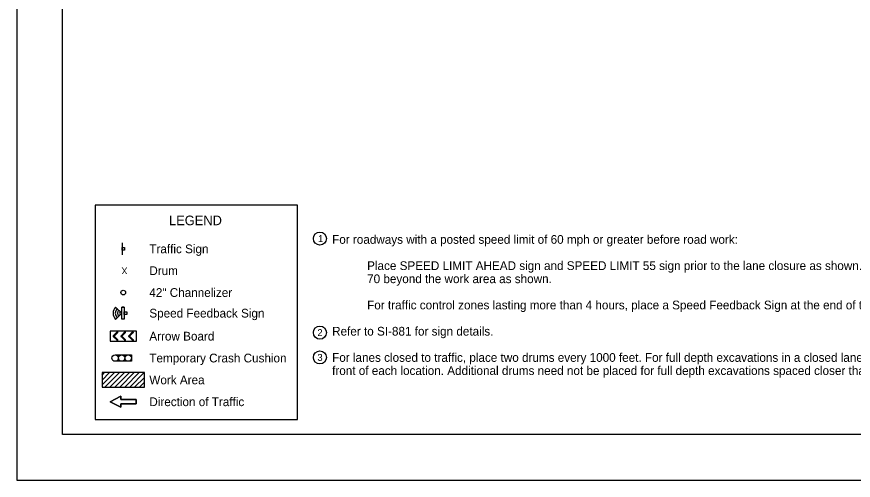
# Model space of a CAD drawing. Extents: x 10133 to 81668, y 4177 to 11018.
# Drawn here: x 28028 to 29940, y 7820 to 8880 of the extents above; entities that cross this region are included whole.
import ezdxf

# ---------------------------------------------------------------- set-up
doc = ezdxf.new("R2010")
doc.units = 0
for name, color, linetype in [('dsnNonPlotable', 7, 'Continuous'), ('dsnStdBlockModified', 7, 'Continuous'), ('dsnStdBorder', 7, 'Continuous'), ('dsnStdLabel', 7, 'Continuous'), ('dsnStdLineWork', 7, 'Continuous'), ('Level 1', 7, 'Continuous'), ('Level 2', 7, 'Continuous'), ('SheetBorder', 7, 'Continuous')]:
    doc.layers.add(name, color=color, linetype=linetype)

msp = doc.modelspace()

# ---------------------------------------------------------------- linework, layer by layer
at = {"layer": 'dsnNonPlotable'}
for p, q in [((28269, 8362.5), (28269, 8335)), ((28273.7, 8215.4), (28273.7, 8187.9)), ((28248.8, 8149.8), (28257.6, 8158.7)), ((28266.4, 8149.8), (28275.2, 8158.7)), ((28284, 8149.8), (28292.8, 8158.7)), ((28252.9, 8106.6), (28290.4, 8106.6)), ((28290.4, 8091.6), (28252.9, 8091.6)), ((28290.4, 8106.6), (28290.4, 8091.6)), ((28223.3, 8060.1), (28228.9, 8065.7)), ((28223.3, 8048.8), (28240.3, 8065.7)), ((28223.3, 8037.5), (28251.6, 8065.7)), ((28229.6, 8032.5), (28262.9, 8065.7)), ((28240.9, 8032.5), (28274.2, 8065.7)), ((28252.2, 8032.5), (28285.5, 8065.7)), ((28263.5, 8032.5), (28296.8, 8065.7)), ((28274.9, 8032.5), (28308.1, 8065.7)), ((28286.2, 8032.5), (28319.5, 8065.7)), ((28297.5, 8032.5), (28319.9, 8054.9)), ((28308.8, 8032.5), (28319.9, 8043.6))]:
    msp.add_line(p, q, dxfattribs=at)
for points in [[(28269.1, 8346.1), (28269.1, 8351.7), (28274.7, 8351.7), (28274.7, 8346.1)], [(28268.1, 8187.9), (28268.1, 8215.4), (28273.7, 8215.4), (28273.7, 8187.9)], [(28273.7, 8199), (28273.7, 8204.6), (28279.3, 8204.6), (28279.3, 8199)], [(28301.6, 8160.6), (28241.6, 8160.6), (28241.6, 8137.6), (28301.6, 8137.6)], [(28223.3, 8065.7), (28223.3, 8032.5), (28319.9, 8032.5), (28319.9, 8065.7)], [(28301.3, 8004.1), (28301.3, 7994.1), (28266.3, 7994.1), (28266.3, 7986.6), (28241.3, 7999.1), (28266.3, 8011.6), (28266.3, 8004.1)]]:
    msp.add_lwpolyline(points, close=True, dxfattribs=at)
for points in [[(28257.7, 8139.5), (28257.6, 8139.6), (28248.8, 8148.4), (28248.8, 8148.4)], [(28259.1, 8157.2), (28259.1, 8157.2), (28250.6, 8149.1), (28259.1, 8141)], [(28275.2, 8139.5), (28275.2, 8139.6), (28266.4, 8148.4), (28266.4, 8148.4)], [(28276.6, 8157.2), (28276.6, 8157.2), (28268.1, 8149.1), (28276.6, 8141)], [(28292.9, 8139.5), (28292.8, 8139.6), (28284, 8148.4), (28284, 8148.4)], [(28294.3, 8157.2), (28294.3, 8157.2), (28285.8, 8149.1), (28294.3, 8141)], [(28266.3, 8004.1), (28266.3, 8011.6), (28241.3, 7999.1), (28266.3, 7986.6), (28266.3, 7994.1), (28301.3, 7994.1), (28301.3, 8004.1), (28266.3, 8004.1)]]:
    msp.add_lwpolyline(points, dxfattribs=at)
for centre, radius in [((28271.6, 8248.9), 5.37), ((28271.6, 8248.9), 5.37), ((28252.9, 8099.1), 7.5), ((28252.9, 8099.1), 7.5), ((28267.9, 8099.1), 7.5), ((28267.9, 8099.1), 7.5), ((28282.9, 8099.1), 7.5), ((28282.9, 8099.1), 7.5)]:
    msp.add_circle(centre, radius, dxfattribs=at)
for centre, start, end in [((28249.6, 8149.1), 134.1616, 224.6098), ((28258.4, 8157.9), 315.0975, 135.281), ((28267.1, 8149.1), 134.1616, 224.6098), ((28275.9, 8157.9), 315.0975, 135.281), ((28284.7, 8149.1), 134.1616, 224.6098), ((28293.6, 8157.9), 315.0975, 135.281), ((28258.4, 8140.3), 226.201, 47.3602), ((28275.9, 8140.3), 226.201, 47.3602), ((28293.6, 8140.3), 226.201, 47.3602)]:
    msp.add_arc(centre, 1.03, start, end, dxfattribs=at)
at = {"layer": 'dsnStdBlockModified'}
msp.add_lwpolyline([(28132.5, 9934), (31267.5, 9934), (31267.5, 7924), (28132.5, 7924)], close=True, dxfattribs=at)
at = {"layer": 'dsnStdBorder'}
msp.add_lwpolyline([(28028, 7819.5), (31372, 7819.5), (31372, 10403.5), (28028, 10403.5)], close=True, dxfattribs=at)
at = {"layer": 'dsnStdLabel'}
msp.add_lwpolyline([(28207.5, 8448.9), (28207.5, 7958.6), (28669.4, 7958.6), (28669.4, 8448.9), (28207.5, 8448.9)], dxfattribs=at)
at = {"layer": 'dsnStdLineWork'}
for p, q in [((28253.9, 8215.8), (28268.1, 8201.7)), ((28273.7, 8215.4), (28268.1, 8215.4)), ((28268.1, 8201.7), (28253.9, 8187.5)), ((28273.7, 8187.9), (28268.1, 8187.9))]:
    msp.add_line(p, q, dxfattribs=at)
for radius, start, end in [(20.3, 135.88, 224.0313), (15.3, 136.1665, 223.7159), (10.3, 136.7294, 223.0963), (5.32, 138.7005, 221.2995)]:
    msp.add_arc((28268.5, 8201.7), radius, start, end, dxfattribs=at)
at = {"layer": 'Level 2'}
for centre in [(28721, 8372.3), (28721, 8157.2), (28721, 8100.5)]:
    msp.add_circle(centre, 15, dxfattribs=at)
at = {"layer": 'SheetBorder'}
msp.add_lwpolyline([(28132.5, 9944), (31267.5, 9944), (31267.5, 7924), (28132.5, 7924)], close=True, dxfattribs=at)

# ---------------------------------------------------------------- texts
at = {"layer": 'dsnNonPlotable'}
for s, height, p in [('LEGEND', 22, (28376.1, 8402.9)), ('Traffic Sign', 20, (28331.1, 8338.8)), ('Drum', 20, (28331.1, 8288.9)), ('42" Channelizer ', 20, (28331.1, 8238.9)), ('Speed Feedback Sign', 20, (28331.1, 8191.7)), ('Arrow Board', 20, (28331.1, 8139.1)), ('Temporary Crash Cushion', 20, (28331.1, 8089.1)), ('Work Area', 20, (28331.1, 8039.1)), ('Direction of Traffic', 20, (28331.1, 7989.1))]:
    msp.add_text(s, height=height, dxfattribs=at).set_placement(p)
msp.add_text('X', height=15, rotation=180, dxfattribs=at).set_placement((28281, 8306.4))
at = {"layer": 'Level 1'}
for s, p in [('For roadways with a posted speed limit of 60 mph or greater before road work:', (28748.9, 8360.4)), ('Place SPEED LIMIT AHEAD sign and SPEED LIMIT 55 sign prior to the lane closure as shown. Place SPEED LIMIT', (28828.9, 8300.4)), ('70 beyond the work area as shown.', (28828.9, 8270.4)), ('For traffic control zones lasting more than 4 hours, place a Speed Feedback Sign at the end of the merge taper.', (28828.9, 8210.4)), ('Refer to SI-881 for sign details.', (28748.9, 8150.4)), ('For lanes closed to traffic, place two drums every 1000 feet. For full depth excavations in a closed lane, place two drums in ', (28748.9, 8090.4)), ('front of each location. Additional drums need not be placed for full depth excavations spaced closer than 150 feet.', (28748.9, 8060.4))]:
    msp.add_text(s, height=20, dxfattribs=at).set_placement(p)
at = {"layer": 'Level 2'}
for s, p in [('1', (28716.8, 8364.3)), ('2', (28715.3, 8149.2)), ('3', (28715.3, 8092.5))]:
    msp.add_text(s, height=16, dxfattribs=at).set_placement(p)

doc.saveas('drawing.dxf')
